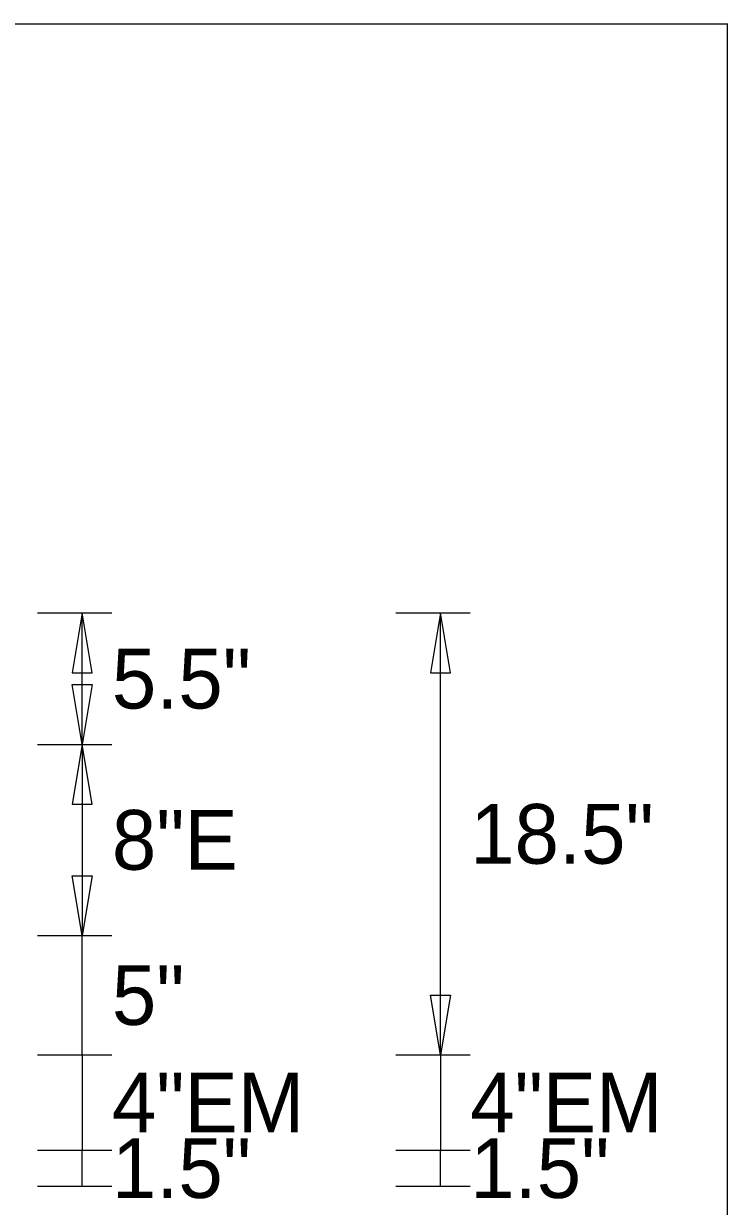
# Model space of a CAD drawing. Extents: x -998.8 to -961.2, y -2311.8 to -2287.8.
# Drawn here: x -982.607 to -980.149, y -2303.817 to -2299.689 of the extents above; entities that cross this region are included whole.
import ezdxf

# ---------------------------------------------------------------- set-up
doc = ezdxf.new("R2010")
doc.units = 0
doc.layers.add('GSDims', color=7, linetype='Continuous')
doc.layers.add('SheetLinesMisc2_dp', color=7, linetype='Continuous')

msp = doc.modelspace()

# ---------------------------------------------------------------- linework, layer by layer
at = {"layer": 'GSDims'}
for p, q in [((-982.5595, -2301.7457), (-982.2991, -2301.7457)), ((-982.4033, -2302.2042), (-982.4033, -2301.7457)), ((-981.3077, -2301.7457), (-981.0473, -2301.7457)), ((-981.1514, -2303.2874), (-981.1514, -2301.7457)), ((-982.5595, -2302.2042), (-982.2991, -2302.2042)), ((-982.5595, -2302.2042), (-982.2991, -2302.2042)), ((-982.4033, -2302.2042), (-982.4033, -2302.8708)), ((-982.5595, -2302.8708), (-982.2991, -2302.8708)), ((-982.5595, -2302.8708), (-982.2991, -2302.8708)), ((-982.4033, -2303.2874), (-982.4033, -2302.8708)), ((-982.5595, -2303.2874), (-982.2991, -2303.2874)), ((-982.5595, -2303.2874), (-982.2991, -2303.2874)), ((-982.4033, -2303.2874), (-982.4033, -2303.6207)), ((-981.3077, -2303.2874), (-981.0473, -2303.2874)), ((-981.3077, -2303.2874), (-981.0473, -2303.2874)), ((-981.1514, -2303.2874), (-981.1514, -2303.6208)), ((-982.5595, -2303.6207), (-982.2991, -2303.6207)), ((-982.5595, -2303.6207), (-982.2991, -2303.6207)), ((-982.4033, -2303.7458), (-982.4033, -2303.6207)), ((-981.3077, -2303.6208), (-981.0473, -2303.6208)), ((-981.3077, -2303.6208), (-981.0473, -2303.6208)), ((-981.1514, -2303.7458), (-981.1514, -2303.6208)), ((-982.5595, -2303.7458), (-982.2991, -2303.7458)), ((-981.3077, -2303.7458), (-981.0473, -2303.7458))]:
    msp.add_line(p, q, dxfattribs=at)
for points in [[(-982.4033, -2301.7457), (-982.438, -2301.9541), (-982.3686, -2301.9541)], [(-981.1514, -2301.7457), (-981.1862, -2301.9541), (-981.1167, -2301.9541)], [(-982.4033, -2302.2042), (-982.438, -2301.9958), (-982.3686, -2301.9958)], [(-982.4033, -2302.2042), (-982.438, -2302.4125), (-982.3686, -2302.4125)], [(-982.4033, -2302.8708), (-982.438, -2302.6625), (-982.3686, -2302.6625)], [(-981.1514, -2303.2874), (-981.1862, -2303.0791), (-981.1167, -2303.0791)]]:
    msp.add_lwpolyline(points, close=True, dxfattribs=at)
at = {"layer": 'SheetLinesMisc2_dp'}
for p, q in [((-992.9403, -2299.6892), (-980.149, -2299.6892)), ((-980.149, -2305.9109), (-980.149, -2299.6888))]:
    msp.add_line(p, q, dxfattribs=at)

# ---------------------------------------------------------------- texts
at = {"layer": 'GSDims'}
for s, p in [('5.5"', (-982.2991, -2302.0791)), ('8"E', (-982.2991, -2302.6417)), ('18.5"', (-981.0473, -2302.6207)), ('5"', (-982.2991, -2303.1833)), ('4"EM', (-982.2991, -2303.5582)), ('4"EM', (-981.0473, -2303.5583)), ('1.5"', (-982.2991, -2303.7874)), ('1.5"', (-981.0473, -2303.7874))]:
    msp.add_text(s, height=0.20833, dxfattribs=at).set_placement(p)

doc.saveas('drawing.dxf')
